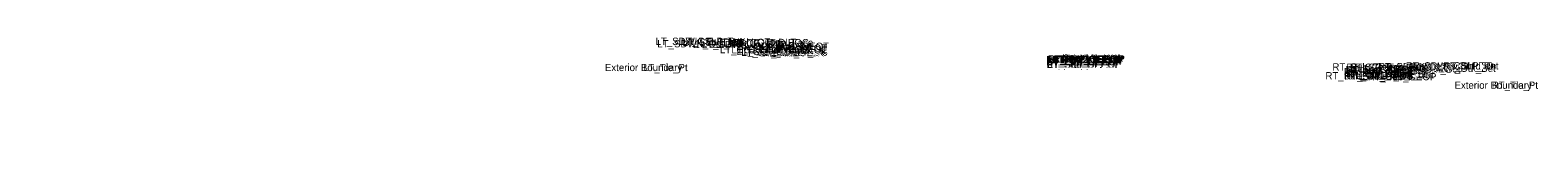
# Model space of a CAD drawing. Extents: x -26 to 6300, y -10 to 9528.
# Drawn here: x 1000 to 1208.7, y 4000 to 4016.7 of the extents above; entities that cross this region are included whole.
import ezdxf

# ---------------------------------------------------------------- set-up
doc = ezdxf.new("R2010")
doc.units = 0
doc.layers.add('Default', color=7, linetype='Continuous')

msp = doc.modelspace()

# ---------------------------------------------------------------- texts
at = {"layer": 'Default'}
for s, height, p in [('LT_SDWK_Out_Top', 1, (1086.58, 4015.72)), ('LT_SDWK_Out_Bot', 1, (1086.83, 4015.38)), ('LT_CSLP_Pnt', 1, (1090.1, 4015.72)), ('LT_Sub_Trench_Out_DLT', 1, (1090.32, 4015.57)), ('LT_SDWK_In_Top', 1, (1092.74, 4015.62)), ('LT_SDWK_In_Bot', 1, (1092.99, 4015.28)), ('LT_CG_Top_BOC', 1, (1096.81, 4015.53)), ('LT_CG_Top_Face', 1, (1097.34, 4015.53)), ('LT_CG_Top_Gut', 1, (1097.87, 4015.03)), ('LT_PV1_OEOT', 1, (1101.23, 4015.03)), ('LT_CG1_Shelf_Out', 1, (1095.48, 4014.56)), ('LT_CG_Bot_BOC', 1, (1097.09, 4014.54)), ('LT_Sub_OEOP', 1, (1097.79, 4014.32)), ('LT_Sub_OEOT_CG', 1, (1098.44, 4014.19)), ('LT_PV2_OEOT', 1, (1100.99, 4014.78)), ('LT_PV3_OEOT', 1, (1100.99, 4014.53)), ('LT_Sub_OEOT', 1, (1101.04, 4014.15)), ('LT_CG_Bot_IE', 1, (1101.34, 4014.44)), ('RT_PV2_OEEOP', 1, (1140.67, 4013.16)), ('RT_PV3_OEEOP', 1, (1140.67, 4012.91)), ('LT_PV2_OEEOP', 1, (1140.79, 4013.16)), ('LT_PV3_OEEOP', 1, (1140.79, 4012.91)), ('RT_PV1_OEEOP', 1, (1140.91, 4013.28)), ('LT_PV1_OEEOP', 1, (1141.03, 4013.28)), ('RT_PV2_IEEOP', 1, (1141.43, 4013.16)), ('LT_PV2_IEEOP', 1, (1141.55, 4013.16)), ('RT_PV1_IEEOP', 1, (1141.67, 4013.28)), ('LT_PV1_IEEOP', 1, (1141.79, 4013.28)), ('RT_PV2_PGL', 1, (1142.65, 4013.16)), ('LT_PV2_PGL', 1, (1142.77, 4013.16)), ('RT_PV1_PGL', 1, (1142.89, 4013.41)), ('LT_PV1_PGL', 1, (1143.01, 4013.41)), ('Exterior Boundary', 1, (1079.57, 4012.09)), ('LT_Tie_Pt', 1, (1084.85, 4012.09)), ('RT_Sub_OEEOP', 1, (1140.72, 4012.53)), ('LT_Sub_OEEOP', 1, (1140.83, 4012.53)), ('RT_Sub_OEOT_CG', 1, (1179.32, 4010.95)), ('RT_Sub_Trench_Out_DLT', 1, (1180.29, 4012.17)), ('RT_PV2_OEOT', 1, (1181.87, 4011.54)), ('RT_PV3_OEOT', 1, (1181.87, 4011.29)), ('RT_Sub_OEOT', 1, (1181.92, 4010.91)), ('RT_PV1_OEOT', 1, (1182.11, 4011.79)), ('RT_CG_Bot_IE', 1, (1182.22, 4011.2)), ('RT_CG_Top_Face', 1, (1182.23, 4012.13)), ('RT_CG1_Shelf_Out', 1, (1182.36, 4011.08)), ('RT_CG_Top_BOC', 1, (1182.7, 4012.13)), ('RT_CG_Top_Gut', 1, (1182.75, 4011.63)), ('RT_CG_Bot_BOC', 1, (1182.97, 4011.1)), ('RT_Sub_OEOP', 1, (1185.17, 4010.82)), ('RT_SDWK_In_Top', 1, (1186.62, 4012.22)), ('RT_SDWK_In_Bot', 1, (1186.87, 4011.88)), ('RT_SDWK_Out_Top', 1, (1190.47, 4012.32)), ('RT_SDWK_Out_Bot', 1, (1190.71, 4011.98)), ('RT_Shld_O', 1, (1195.63, 4012.31)), ('CSLP_Pnt', 1, (1197.04, 4012.32)), ('Exterior Boundary', 1, (1197.19, 4009.64)), ('RT_Tie_Pt', 1, (1202.35, 4009.64)), ('-', 0.0001, (1000, 4000))]:
    msp.add_text(s, height=height, dxfattribs=at).set_placement(p)

doc.saveas('drawing.dxf')
